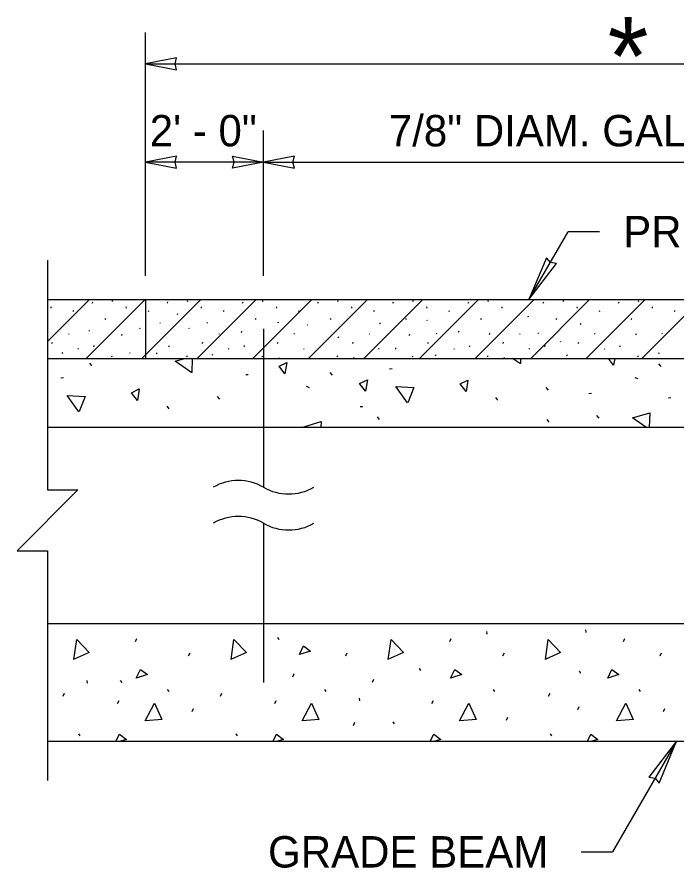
# Model space of a CAD drawing. Extents: x 99862 to 104211, y 98939 to 105076.
# Drawn here: x 100460.6 to 100796.6, y 103696.8 to 104130.2 of the extents above; entities that cross this region are included whole.
import ezdxf

# ---------------------------------------------------------------- set-up
doc = ezdxf.new("R2010")
doc.units = 0
for name, color, linetype in [('Level 10', 7, 'Continuous'), ('Level 12', 7, 'Continuous'), ('Level 15', 7, 'Continuous'), ('Level 20', 7, 'Continuous'), ('Level 26', 7, 'Continuous'), ('Level 3', 7, 'Continuous'), ('Level 6', 7, 'Continuous')]:
    doc.layers.add(name, color=color, linetype=linetype)

msp = doc.modelspace()

# ---------------------------------------------------------------- linework, layer by layer
at = {"layer": 'Level 10'}
for p, q in [((100586.13, 103971.29), (100586.13, 103890.67)), ((100586.13, 103872.35), (100586.13, 103791.29))]:
    msp.add_line(p, q, dxfattribs=at)
at = {"layer": 'Level 12'}
for p, q in [((100476.13, 103821.29), (101416.13, 103821.29)), ((100476.13, 103761.29), (101416.13, 103761.29))]:
    msp.add_line(p, q, dxfattribs=at)
at = {"layer": 'Level 15'}
for p, q in [((100526.13, 103998.29), (100526.13, 104122.29)), ((100526.13, 104106.29), (101366.13, 104106.29)), ((100586.13, 103998.29), (100586.13, 104072.29)), ((100586.13, 104056.29), (100526.13, 104056.29)), ((100586.13, 104056.29), (101306.13, 104056.29)), ((100721.26, 103986.29), (100741.2, 104020.83)), ((100757.2, 104020.83), (100741.2, 104020.83)), ((100796.33, 103761.29), (100763.83, 103705)), ((100747.83, 103705), (100763.83, 103705))]:
    msp.add_line(p, q, dxfattribs=at)
for points in [[(100526.13, 104106.29), (100541.86, 104103.21), (100541.13, 104106.29), (100541.86, 104109.37)], [(100526.13, 104056.29), (100541.86, 104053.21), (100541.13, 104056.29), (100541.86, 104059.37)], [(100586.13, 104056.29), (100570.41, 104053.21), (100571.14, 104056.29), (100570.41, 104059.37)], [(100586.13, 104056.29), (100601.86, 104053.21), (100601.13, 104056.29), (100601.86, 104059.37)], [(100721.26, 103986.29), (100735.26, 104004.57), (100732.15, 104005.15), (100730.09, 104007.55)], [(100796.33, 103761.29), (100782.33, 103743.01), (100785.44, 103742.43), (100787.5, 103740.03)]]:
    msp.add_lwpolyline(points, close=True, dxfattribs=at)
msp.add_lwpolyline([(100476.13, 104006.29), (100476.13, 103889.28), (100491.62, 103889.28), (100460.65, 103858.3), (100476.13, 103858.3), (100476.13, 103741.29)], dxfattribs=at)
for centre, start, end in [((100573.34, 103868.51), 60, 120), ((100598.93, 103912.83), 240, 300), ((100573.34, 103850.19), 60, 120), ((100598.93, 103894.51), 240, 300)]:
    msp.add_arc(centre, 25.59, start, end, dxfattribs=at)
at = {"layer": 'Level 26'}
for p, q in [((100476.13, 103964.86), (100497.56, 103986.29)), ((100495.85, 103956.29), (100525.85, 103986.29)), ((100498.95, 103984.4), (100499.24, 103985.04)), ((100508.93, 103985.79), (100509.22, 103985.36)), ((100524.13, 103956.29), (100554.13, 103986.29)), ((100537.22, 103984.4), (100537.5, 103985.04)), ((100547.2, 103985.79), (100547.48, 103985.36)), ((100552.41, 103956.29), (100582.41, 103986.29)), ((100575.48, 103984.4), (100575.77, 103985.04)), ((100580.7, 103956.29), (100610.7, 103986.29)), ((100585.46, 103985.79), (100585.75, 103985.36)), ((100608.98, 103956.29), (100638.98, 103986.29)), ((100613.74, 103984.4), (100614.03, 103985.04)), ((100623.72, 103985.79), (100624.01, 103985.36)), ((100637.27, 103956.29), (100667.27, 103986.29)), ((100652.01, 103984.4), (100652.3, 103985.04)), ((100661.99, 103985.79), (100662.28, 103985.36)), ((100665.55, 103956.29), (100695.55, 103986.29)), ((100690.27, 103984.4), (100690.56, 103985.04)), ((100693.83, 103956.29), (100723.83, 103986.29)), ((100700.25, 103985.79), (100700.54, 103985.36)), ((100722.12, 103956.29), (100752.12, 103986.29)), ((100728.54, 103984.4), (100728.82, 103985.04)), ((100738.52, 103985.79), (100738.8, 103985.36)), ((100750.4, 103956.29), (100780.4, 103986.29)), ((100766.8, 103984.4), (100767.09, 103985.04)), ((100776.78, 103985.79), (100777.07, 103985.36)), ((100778.69, 103956.29), (100808.69, 103986.29)), ((100477.79, 103982.59), (100477.86, 103981.94)), ((100489.07, 103980.68), (100489.35, 103980.25)), ((100516.05, 103982.59), (100516.13, 103981.94)), ((100527.33, 103980.68), (100527.62, 103980.25)), ((100554.32, 103982.59), (100554.39, 103981.94)), ((100565.59, 103980.68), (100565.88, 103980.25)), ((100592.58, 103982.59), (100592.65, 103981.94)), ((100603.86, 103980.68), (100604.15, 103980.25)), ((100630.85, 103982.59), (100630.92, 103981.94)), ((100642.12, 103980.68), (100642.41, 103980.25)), ((100669.11, 103982.59), (100669.18, 103981.94)), ((100680.39, 103980.68), (100680.67, 103980.25)), ((100707.37, 103982.59), (100707.45, 103981.94)), ((100745.64, 103982.59), (100745.71, 103981.94)), ((100756.91, 103980.68), (100757.2, 103980.25)), ((100783.9, 103982.59), (100783.97, 103981.94)), ((100795.18, 103980.68), (100795.47, 103980.25)), ((100505.5, 103976.05), (100505.79, 103976.7)), ((100542.27, 103978.58), (100542.56, 103979.23)), ((100582.03, 103976.05), (100582.31, 103976.7)), ((100620.29, 103976.05), (100620.58, 103976.7)), ((100658.55, 103976.05), (100658.84, 103976.7)), ((100669.22, 103975.95), (100669.51, 103975.52)), ((100696.82, 103976.05), (100697.11, 103976.7)), ((100720.61, 103977.94), (100720.9, 103977.51)), ((100735.08, 103976.05), (100735.37, 103976.7)), ((100773.35, 103976.05), (100773.63, 103976.7)), ((100522.96, 103971.77), (100523.25, 103971.34)), ((100533.28, 103974.64), (100533.57, 103974.21)), ((100548.05, 103971.88), (100548.34, 103971.45)), ((100557.34, 103974.66), (100557.63, 103974.22)), ((100593.34, 103974.91), (100593.62, 103974.48)), ((100608.26, 103973.62), (100608.55, 103973.19)), ((100645.16, 103974.41), (100645.45, 103973.98)), ((100747.29, 103974.07), (100747.58, 103973.63)), ((100486.8, 103969.02), (100487.08, 103968.59)), ((100497.2, 103970.54), (100497.48, 103970.11)), ((100513.95, 103967.94), (100514.24, 103968.59)), ((100563.32, 103969.02), (100563.61, 103968.59)), ((100574.86, 103969.57), (100575.15, 103970.22)), ((100601.59, 103969.02), (100601.87, 103968.59)), ((100624.12, 103966.8), (100624.41, 103967.45)), ((100639.85, 103969.02), (100640.14, 103968.59)), ((100660.37, 103967.97), (100660.66, 103968.62)), ((100674.02, 103969.18), (100674.31, 103968.75)), ((100685.27, 103970.09), (100685.55, 103969.65)), ((100701.1, 103968.55), (100701.38, 103969.2)), ((100716.38, 103969.02), (100716.67, 103968.59)), ((100725.83, 103969.34), (100726.12, 103968.91)), ((100754.64, 103969.02), (100754.93, 103968.59)), ((100775.68, 103968.28), (100775.97, 103968.93)), ((100788.81, 103969.18), (100789.1, 103968.75)), ((100478.45, 103963.85), (100478.74, 103964.5)), ((100499.67, 103962.2), (100499.96, 103962.84)), ((100537.93, 103962.2), (100538.22, 103962.84)), ((100554.98, 103963.85), (100555.27, 103964.5)), ((100576.2, 103962.2), (100576.49, 103962.84)), ((100593.25, 103963.85), (100593.53, 103964.5)), ((100631.51, 103963.85), (100631.8, 103964.5)), ((100669.77, 103963.85), (100670.06, 103964.5)), ((100690.99, 103962.2), (100691.28, 103962.84)), ((100708.04, 103963.85), (100708.33, 103964.5)), ((100729.25, 103962.2), (100729.54, 103962.84)), ((100737.08, 103965.09), (100737.36, 103964.66)), ((100746.3, 103963.85), (100746.59, 103964.5)), ((100767.52, 103962.2), (100767.81, 103962.84)), ((100483.45, 103959.25), (100483.74, 103958.82)), ((100491.62, 103961.36), (100491.91, 103960.92)), ((100517.86, 103959.33), (100518.15, 103958.9)), ((100531.54, 103959.12), (100531.82, 103958.69)), ((100559.92, 103958.42), (100560.21, 103957.99)), ((100568.15, 103961.36), (100568.44, 103960.92)), ((100606.41, 103961.36), (100606.7, 103960.92)), ((100644.68, 103961.36), (100644.96, 103960.92)), ((100653.27, 103961.72), (100653.34, 103961.07)), ((100673.48, 103958.08), (100673.77, 103957.65)), ((100682.94, 103961.36), (100683.23, 103960.92)), ((100721.2, 103961.36), (100721.49, 103960.92)), ((100740.41, 103958.11), (100740.7, 103957.67)), ((100759.47, 103961.36), (100759.76, 103960.92)), ((100787.15, 103959.25), (100787.43, 103958.82)), ((100498.75, 103952.59), (100497.65, 103953.95)), ((100508.66, 103957.59), (100508.95, 103957.16)), ((100546.93, 103957.59), (100547.21, 103957.16)), ((100585.19, 103957.59), (100585.48, 103957.16)), ((100593.69, 103956.81), (100593.98, 103956.38)), ((100623.45, 103957.59), (100623.74, 103957.16)), ((100631.95, 103956.81), (100632.24, 103956.38)), ((100661.72, 103957.59), (100662.01, 103957.16)), ((100699.98, 103957.59), (100700.27, 103957.16)), ((100708.48, 103956.81), (100708.77, 103956.38)), ((100776.51, 103957.59), (100776.8, 103957.16)), ((100788.52, 103952.23), (100787.42, 103953.59)), ((100650.28, 103950.99), (100651.55, 103951.13)), ((100482.97, 103946.45), (100484.25, 103946.6)), ((100577.04, 103948.02), (100578.31, 103948.17)), ((100621.21, 103947.69), (100620.11, 103949.05)), ((100775.09, 103946.64), (100776.6, 103946.08)), ((100607.79, 103942.1), (100609.29, 103941.54)), ((100731.14, 103940.11), (100730.04, 103941.47)), ((100563.83, 103935.58), (100562.73, 103936.94)), ((100705.45, 103935.07), (100704.35, 103936.43)), ((100751.76, 103938.38), (100753.03, 103938.53)), ((100792.21, 103936.24), (100793.48, 103936.39)), ((100538.14, 103930.53), (100537.04, 103931.89)), ((100635.39, 103931.72), (100636.67, 103931.87)), ((100645.21, 103925.21), (100644.11, 103926.57)), ((100731.56, 103923.76), (100730.45, 103925.12)), ((100756.97, 103925.81), (100755.87, 103927.17)), ((100699.65, 103817.19), (100699.8, 103815.85)), ((100749.97, 103818.04), (100750.12, 103816.69)), ((100521.01, 103812.12), (100521.72, 103813.72)), ((100593.22, 103814.26), (100593.93, 103813.2)), ((100681.01, 103812.12), (100681.72, 103813.72)), ((100769.34, 103812.12), (100770.05, 103813.72)), ((100548.01, 103804.83), (100548.72, 103806.43)), ((100628.01, 103804.83), (100628.72, 103806.43)), ((100708.01, 103804.83), (100708.72, 103806.43)), ((100788.01, 103804.83), (100788.72, 103806.43)), ((100665.37, 103798.33), (100666.08, 103797.27)), ((100601.01, 103794.16), (100601.72, 103795.76)), ((100746.79, 103797.12), (100747.5, 103796.06)), ((100496.23, 103792.27), (100496.38, 103790.92)), ((100513.22, 103792.23), (100513.93, 103791.16)), ((100641.65, 103791.39), (100642.36, 103792.99)), ((100484.17, 103784.23), (100484.88, 103785.83)), ((100537.14, 103787.71), (100537.85, 103786.64)), ((100564.17, 103784.23), (100564.88, 103785.83)), ((100617.14, 103787.71), (100617.85, 103786.64)), ((100703, 103787.71), (100703.71, 103786.64)), ((100731.26, 103784.23), (100731.97, 103785.83)), ((100777.14, 103787.71), (100777.85, 103786.64)), ((100511.87, 103780.52), (100512.59, 103782.12)), ((100591.87, 103780.52), (100592.59, 103782.12)), ((100634.76, 103783.19), (100634.91, 103781.84)), ((100671.87, 103780.52), (100672.59, 103782.12)), ((100549.78, 103776.44), (100550.49, 103778.04)), ((100746.14, 103777.44), (100746.85, 103779.04)), ((100789.78, 103776.44), (100790.49, 103778.04)), ((100709.78, 103771.98), (100710.49, 103773.58)), ((100631.88, 103769.4), (100632.6, 103770.99)), ((100651.98, 103771.24), (100652.69, 103770.17)), ((100491.98, 103765.07), (100492.69, 103764.01)), ((100571.98, 103765.07), (100572.69, 103764.01)), ((100731.98, 103765.07), (100732.69, 103764.01))]:
    msp.add_line(p, q, dxfattribs=at)
for points in [[(100549.59, 103948.95), (100541.18, 103954.81), (100546, 103956.29)], [(100549.88, 103956.29), (100549.61, 103949.12)], [(100597.03, 103948.36), (100594.05, 103952.27), (100598.03, 103954.23), (100597.03, 103948.36)], [(100716.9, 103953.49), (100712.88, 103956.29)], [(100717.02, 103956.29), (100716.92, 103953.66)], [(100764.34, 103952.9), (100761.75, 103956.29)], [(100764.92, 103956.29), (100764.34, 103952.9)], [(100637.99, 103939.54), (100635, 103943.46), (100638.99, 103945.41), (100637.99, 103939.54)], [(100689.21, 103939.39), (100686.22, 103943.31), (100690.21, 103945.26), (100689.21, 103939.39)], [(100521.9, 103934.86), (100518.92, 103938.77), (100522.9, 103940.72), (100521.9, 103934.86)], [(100659.45, 103933.59), (100653.56, 103941.97), (100662.69, 103941.51), (100659.53, 103933.75)], [(100492.14, 103929.05), (100486.25, 103937.44), (100495.38, 103936.97), (100492.22, 103929.21)], [(100780.71, 103921.29), (100773.99, 103925.98), (100782.72, 103928.66), (100782.45, 103921.29)], [(100606.89, 103921.29), (100606.68, 103921.44), (100615.42, 103924.12), (100615.31, 103921.29)], [(100704.49, 103821.27), (100704.5, 103821.29)], [(100704.57, 103821.29), (100704.49, 103821.27)], [(100489.61, 103803), (100491.02, 103813.15), (100497.38, 103806.58), (100489.78, 103803.06)], [(100569.61, 103803), (100571.02, 103813.15), (100577.38, 103806.58), (100569.78, 103803.06)], [(100649.61, 103803), (100651.02, 103813.15), (100657.38, 103806.58), (100649.78, 103803.06)], [(100729.61, 103803), (100731.02, 103813.15), (100737.38, 103806.58), (100729.78, 103803.06)], [(100604.38, 103805.49), (100606.51, 103809.93), (100610.06, 103807.26), (100604.38, 103805.49)], [(100521.37, 103793.47), (100523.5, 103797.91), (100527.05, 103795.24), (100521.37, 103793.47)], [(100681.37, 103793.47), (100683.5, 103797.91), (100687.05, 103795.24), (100681.37, 103793.47)], [(100761.37, 103793.47), (100763.5, 103797.91), (100767.05, 103795.24), (100761.37, 103793.47)], [(100525.81, 103771.65), (100530.6, 103780.7), (100534.33, 103772.36), (100525.98, 103771.65)], [(100605.81, 103771.65), (100610.6, 103780.7), (100614.33, 103772.36), (100605.98, 103771.65)], [(100685.81, 103771.65), (100690.6, 103780.7), (100694.33, 103772.36), (100685.98, 103771.65)], [(100765.81, 103771.65), (100770.6, 103780.7), (100774.33, 103772.36), (100765.98, 103771.65)], [(100511.03, 103761.29), (100512.76, 103764.9), (100516.31, 103762.23), (100513.3, 103761.29)], [(100591.03, 103761.29), (100592.76, 103764.9), (100596.31, 103762.23), (100593.3, 103761.29)], [(100671.03, 103761.29), (100672.76, 103764.9), (100676.31, 103762.23), (100673.3, 103761.29)], [(100751.03, 103761.29), (100752.76, 103764.9), (100756.31, 103762.23), (100753.3, 103761.29)]]:
    msp.add_lwpolyline(points, dxfattribs=at)
at = {"layer": 'Level 3'}
for p, q in [((100476.13, 103986.29), (101416.13, 103986.29)), ((100526.13, 103986.29), (100526.13, 103956.29)), ((100476.13, 103956.29), (101416.13, 103956.29))]:
    msp.add_line(p, q, dxfattribs=at)
at = {"layer": 'Level 6'}
msp.add_line((100476.13, 103921.29), (101416.13, 103921.29), dxfattribs=at)

# ---------------------------------------------------------------- texts
at = {"layer": 'Level 20'}
for s, height, p in [('*', 40, (100761.31, 104090.16)), ('PRECAST CONCRETE FASCIA PANEL', 16, (100769.2, 104012.83))]:
    msp.add_text(s, height=height, rotation=360, dxfattribs=at).set_placement(p)
for s, p in [('2\' - 0"', (100528.2, 104064.29)), ('7/8" DIAM. GALV. ANCHOR ROD @ 4\' - 0\' SPACING MAX.', (100649.9, 104064.29)), ('GRADE BEAM', (100588.42, 103697))]:
    msp.add_text(s, height=16, dxfattribs=at).set_placement(p)

doc.saveas('drawing.dxf')
